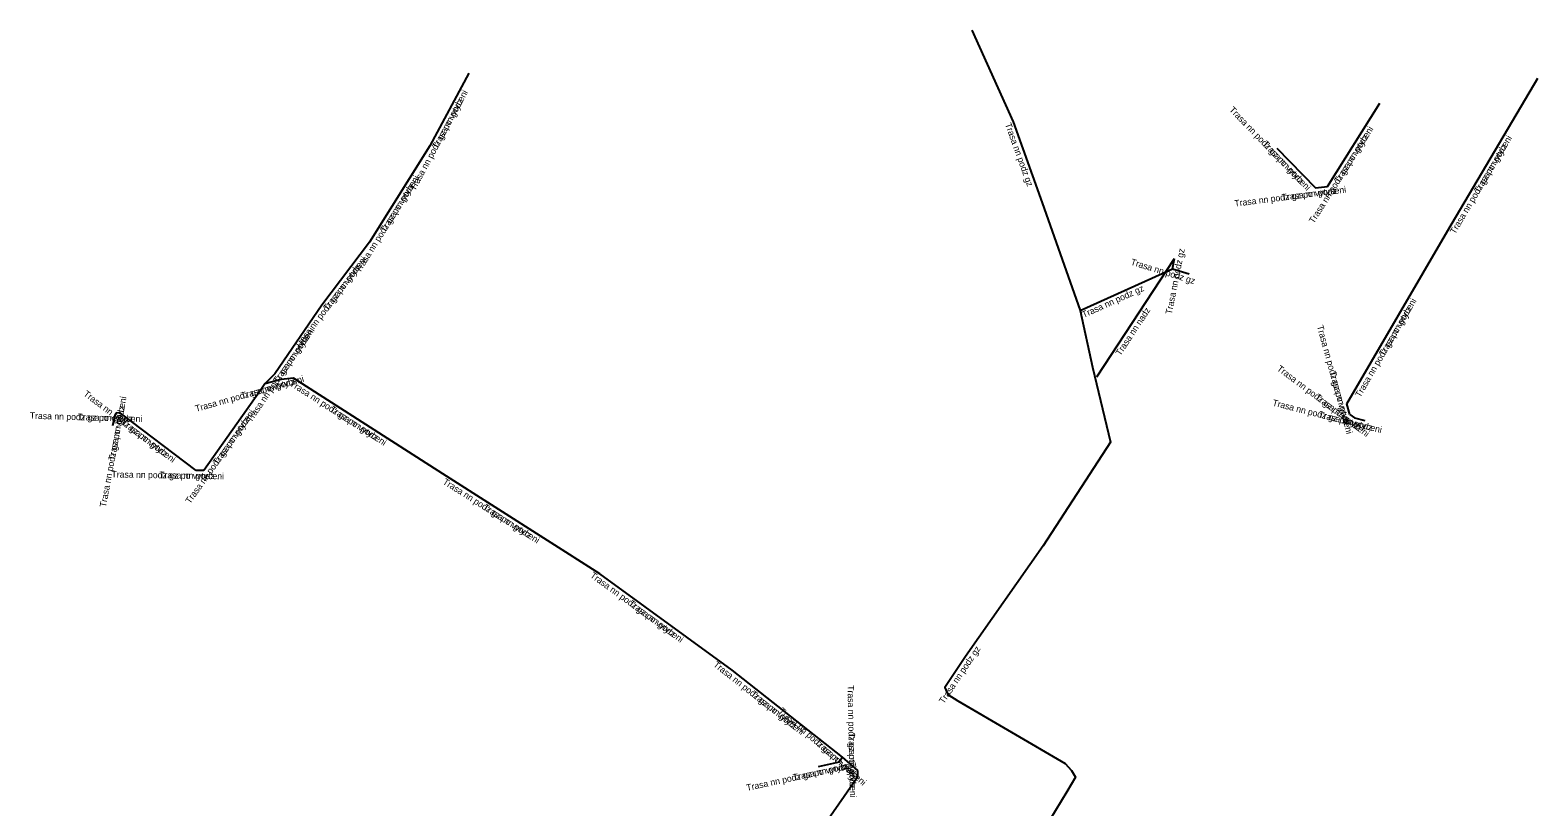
# Model space of a CAD drawing. Extents: x -672293 to -672171, y -1013397 to -1013222.
# Drawn here: x -672292.6 to -672176, y -1013281.7 to -1013221.6 of the extents above; entities that cross this region are included whole.
import ezdxf

# ---------------------------------------------------------------- set-up
doc = ezdxf.new("R2010")
doc.units = 0
doc.layers.add('Popiskový text - Ostatní atributy Trasy', color=7, linetype='Continuous')
doc.layers.add('Spojnice NN', color=7, linetype='Continuous')

msp = doc.modelspace()

# ---------------------------------------------------------------- linework, layer by layer
at = {"layer": 'Spojnice NN'}
for points in [[(-672219.79, -1013221.59), (-672216.6, -1013228.69), (-672214.35, -1013234.96), (-672211.42, -1013243.28)], [(-672258.68, -1013224.91), (-672261.7, -1013230.55)], [(-672258.68, -1013224.91), (-672261.7, -1013230.55)], [(-672182.99, -1013237.1), (-672176.02, -1013225.3)], [(-672182.99, -1013237.1), (-672176.02, -1013225.3)], [(-672192.28, -1013233.68), (-672188.23, -1013227.24)], [(-672192.28, -1013233.68), (-672188.23, -1013227.24)], [(-672261.7, -1013230.55), (-672266.35, -1013237.98)], [(-672261.7, -1013230.55), (-672266.35, -1013237.98)], [(-672196.2, -1013230.71), (-672193.22, -1013233.8)], [(-672196.2, -1013230.71), (-672193.22, -1013233.8)], [(-672193.22, -1013233.8), (-672192.28, -1013233.68)], [(-672193.22, -1013233.8), (-672192.28, -1013233.68)], [(-672190.78, -1013250.51), (-672182.99, -1013237.1)], [(-672190.78, -1013250.51), (-672182.99, -1013237.1)], [(-672266.35, -1013237.98), (-672270.05, -1013242.87)], [(-672266.35, -1013237.98), (-672270.05, -1013242.87)], [(-672210.11, -1013248.41), (-672204.12, -1013239.25)], [(-672204.28, -1013240.05), (-672204.12, -1013239.25)], [(-672211.42, -1013243.28), (-672204.28, -1013240.05)], [(-672204.28, -1013240.05), (-672202.98, -1013240.45)], [(-672270.05, -1013242.87), (-672273.69, -1013248.17), (-672274.45, -1013248.96)], [(-672270.05, -1013242.87), (-672273.69, -1013248.17), (-672274.45, -1013248.96)], [(-672211.42, -1013243.28), (-672210.46, -1013247.66), (-672209.07, -1013253.47), (-672214.26, -1013261.49), (-672220.27, -1013270.05), (-672221.87, -1013272.45), (-672221.65, -1013272.98), (-672220.88, -1013273.48), (-672212.57, -1013278.32), (-672212.07, -1013278.85), (-672211.77, -1013279.37), (-672212.45, -1013280.52), (-672215.95, -1013286.28), (-672216.33, -1013286.81), (-672215.69, -1013287.16), (-672213.67, -1013288.62), (-672211.83, -1013289.8), (-672212.39, -1013290.88)], [(-672272.24, -1013248.5), (-672273.18, -1013248.61), (-672274.45, -1013248.96)], [(-672272.24, -1013248.5), (-672273.18, -1013248.61), (-672274.45, -1013248.96)], [(-672260.7, -1013255.91), (-672272.24, -1013248.5)], [(-672260.7, -1013255.91), (-672272.24, -1013248.5)], [(-672274.45, -1013248.96), (-672274.81, -1013249.49), (-672279.18, -1013255.66)], [(-672274.45, -1013248.96), (-672274.81, -1013249.49), (-672279.18, -1013255.66)], [(-672285.95, -1013251.2), (-672286.06, -1013251.38), (-672286.22, -1013252.21)], [(-672285.95, -1013251.2), (-672286.06, -1013251.38), (-672286.22, -1013252.21)], [(-672285.61, -1013251.21), (-672285.95, -1013251.2)], [(-672285.61, -1013251.21), (-672285.95, -1013251.2)], [(-672279.75, -1013255.65), (-672285.61, -1013251.21)], [(-672279.75, -1013255.65), (-672285.61, -1013251.21)], [(-672190.56, -1013251.31), (-672190.78, -1013250.51)], [(-672190.56, -1013251.31), (-672190.78, -1013250.51)], [(-672190.56, -1013251.31), (-672190.2, -1013251.58)], [(-672190.56, -1013251.31), (-672190.2, -1013251.58)], [(-672190.2, -1013251.58), (-672189.4, -1013251.78)], [(-672190.2, -1013251.58), (-672189.4, -1013251.78)], [(-672279.18, -1013255.66), (-672279.75, -1013255.65)], [(-672279.18, -1013255.66), (-672279.75, -1013255.65)], [(-672248.56, -1013263.64), (-672260.7, -1013255.91)], [(-672248.56, -1013263.64), (-672260.7, -1013255.91)], [(-672238.32, -1013271.11), (-672248.56, -1013263.64)], [(-672238.32, -1013271.11), (-672248.56, -1013263.64)], [(-672229.78, -1013277.83), (-672238.32, -1013271.11)], [(-672229.78, -1013277.83), (-672238.32, -1013271.11)], [(-672229.78, -1013277.83), (-672230.04, -1013278.23), (-672231.68, -1013278.59)], [(-672229.78, -1013277.83), (-672230.04, -1013278.23), (-672231.68, -1013278.59)], [(-672228.61, -1013278.86), (-672229.78, -1013277.83)], [(-672228.61, -1013278.86), (-672229.78, -1013277.83)], [(-672228.6, -1013279.32), (-672228.61, -1013278.86)], [(-672228.6, -1013279.32), (-672228.61, -1013278.86)], [(-672234.89, -1013288.38), (-672228.6, -1013279.32)], [(-672234.89, -1013288.38), (-672228.6, -1013279.32)]]:
    msp.add_lwpolyline(points, dxfattribs=at)

# ---------------------------------------------------------------- texts
at = {"layer": 'Popiskový text - Ostatní atributy Trasy'}
for s, rotation, p in [('Trasa nn podz gz po vytyceni', 61.8327, (-672262.84, -1013234.06)), ('Trasa nn podz', 61.8327, (-672261.1, -1013230.81)), ('Trasa nn podz gz po vytyceni', 313.9604, (-672199.92, -1013227.79)), ('Trasa nn podz gz', 289.7406, (-672217.23, -1013228.87)), ('Trasa nn podz gz po vytyceni', 57.835, (-672193.34, -1013236.59)), ('Trasa nn podz', 313.9604, (-672197.36, -1013230.44)), ('Trasa nn podz', 57.835, (-672191.38, -1013233.47)), ('Trasa nn podz gz po vytyceni', 59.4306, (-672182.42, -1013237.41)), ('Trasa nn podz', 59.4306, (-672180.55, -1013234.24)), ('Trasa nn podz gz po vytyceni', 57.96, (-672267.1, -1013240.4)), ('Trasa nn podz', 57.96, (-672265.14, -1013237.28)), ('Trasa nn podz gz po vytyceni', 7.275, (-672199.45, -1013235.25)), ('Trasa nn podz', 7.275, (-672195.79, -1013234.78)), ('Trasa nn podz gz po vytyceni', 52.8872, (-672271.8, -1013246.27)), ('Trasa nn podz gz', 342.8973, (-672207.54, -1013239.73)), ('Trasa nn podz gz', 78.6901, (-672204.33, -1013243.6)), ('Trasa nn podz', 52.8872, (-672269.58, -1013243.33)), ('Trasa nn podz gz', 24.3411, (-672211.13, -1013243.86)), ('Trasa nn podz gz po vytyceni', 59.8473, (-672189.75, -1013250.04)), ('Trasa nn podz', 59.8473, (-672187.9, -1013246.85)), ('Trasa nn nadz', 56.8151, (-672208.29, -1013246.82)), ('Trasa nn podz gz po vytyceni', 55.519, (-672275.51, -1013251.97)), ('Trasa nn podz', 55.519, (-672273.43, -1013248.94)), ('Trasa nn podz gz po vytyceni', 285.3763, (-672193.11, -1013244.49)), ('Trasa nn podz gz po vytyceni', 323.1301, (-672196.24, -1013247.87)), ('Trasa nn podz gz po vytyceni', 15.6064, (-672279.76, -1013251.12)), ('Trasa nn podz', 15.6064, (-672276.22, -1013250.13)), ('Trasa nn podz gz po vytyceni', 327.2949, (-672272.57, -1013249.06)), ('Trasa nn podz', 285.3763, (-672192.13, -1013248.05)), ('Trasa nn podz gz po vytyceni', 322.8495, (-672288.52, -1013249.82)), ('Trasa nn podz gz po vytyceni', 79.3887, (-672286.74, -1013258.52)), ('Trasa nn podz', 323.1301, (-672193.29, -1013250.08)), ('Trasa nn podz gz po vytyceni', 358.3003, (-672292.63, -1013251.65)), ('Trasa nn podz', 79.3887, (-672286.06, -1013254.9)), ('Trasa nn podz gz po vytyceni', 54.6624, (-672280.23, -1013258.27)), ('Trasa nn podz', 327.2949, (-672269.47, -1013251.05)), ('Trasa nn podz gz po vytyceni', 345.7949, (-672196.58, -1013250.63)), ('Trasa nn podz', 345.7949, (-672193.01, -1013251.54)), ('Trasa nn podz', 358.3003, (-672288.94, -1013251.76)), ('Trasa nn podz', 322.8495, (-672285.58, -1013252.05)), ('Trasa nn podz', 54.6624, (-672278.1, -1013255.26)), ('Trasa nn podz gz po vytyceni', 358.9949, (-672286.31, -1013256.19)), ('Trasa nn podz', 358.9949, (-672282.62, -1013256.25)), ('Trasa nn podz gz po vytyceni', 327.5135, (-672260.74, -1013256.65)), ('Trasa nn podz', 327.5135, (-672257.63, -1013258.63)), ('Trasa nn podz gz po vytyceni', 323.8895, (-672249.34, -1013263.87)), ('Trasa nn podz', 323.8895, (-672246.37, -1013266.04)), ('Trasa nn podz gz', 56.3099, (-672221.95, -1013273.74)), ('Trasa nn podz gz po vytyceni', 321.8013, (-672239.82, -1013270.76)), ('Trasa nn podz', 321.8013, (-672236.93, -1013273.03)), ('Trasa nn podz gz po vytyceni', 271.2454, (-672229.4, -1013272.27)), ('Trasa nn podz gz po vytyceni', 318.6412, (-672234.75, -1013274.32)), ('Trasa nn podz', 318.6412, (-672231.99, -1013276.75)), ('Trasa nn podz', 271.2454, (-672229.32, -1013275.96)), ('Trasa nn podz gz po vytyceni', 12.2698, (-672237.16, -1013280.45)), ('Trasa nn podz', 12.2698, (-672233.56, -1013279.66))]:
    msp.add_text(s, height=0.5, rotation=rotation, dxfattribs=at).set_placement(p)

doc.saveas('drawing.dxf')
